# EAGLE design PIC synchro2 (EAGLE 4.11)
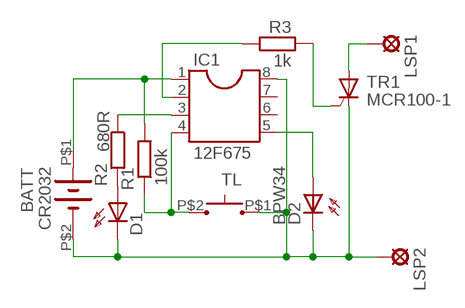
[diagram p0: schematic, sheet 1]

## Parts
BATT  CR2032  BATT_CR2032-1  [CR2032_HOLDER]
D1  LED3MM  [LED3MM]
D2  BPW34  BP104  [BP104]
IC1  12F675  DIL8  [DIL08]
LSP1  LSP13  [LSP13]
LSP2  LSP13  [LSP13]
R1  100k  R10-3  [R10_N]
R2  680R  R10-3  [R10_N]
R3  1k  R10-3  [R10_N]
TL  TLACITKO3-1  [TLACITKO3]
TR1  MCR100-1  [TO92-2]

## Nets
N$1: BATT.P$1(+) IC1.1 R1.2
N$2: BATT.P$2(-) D1.K(C) D2.K(C) IC1.8 LSP2.MP TL.P$1(P) TR1.C
N$3: IC1.2 R3.1
N$5: IC1.3 R2.1
N$6: D1.A R2.2
N$7: R3.2 TR1.G
N$8: D2.A IC1.5
N$10: LSP1.MP TR1.A
N$11: IC1.4 R1.1 TL.P$2(S)
Unconnected: IC1.6 IC1.7

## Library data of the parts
BATT = dusan:BATT_CR2032
D1 = led:LED3MM: LED
D2 = opto-trans-siemens:BP104: PHOTO DIODE
IC1 = dil:DIL8: SOCKET DIL8
LSP1 LSP2 = solpad:LSP13: SOLDER PAD
R1-R3 = dusan:R10
TL = dusan:TLACITKO3
TR1 = dusan:MCR100

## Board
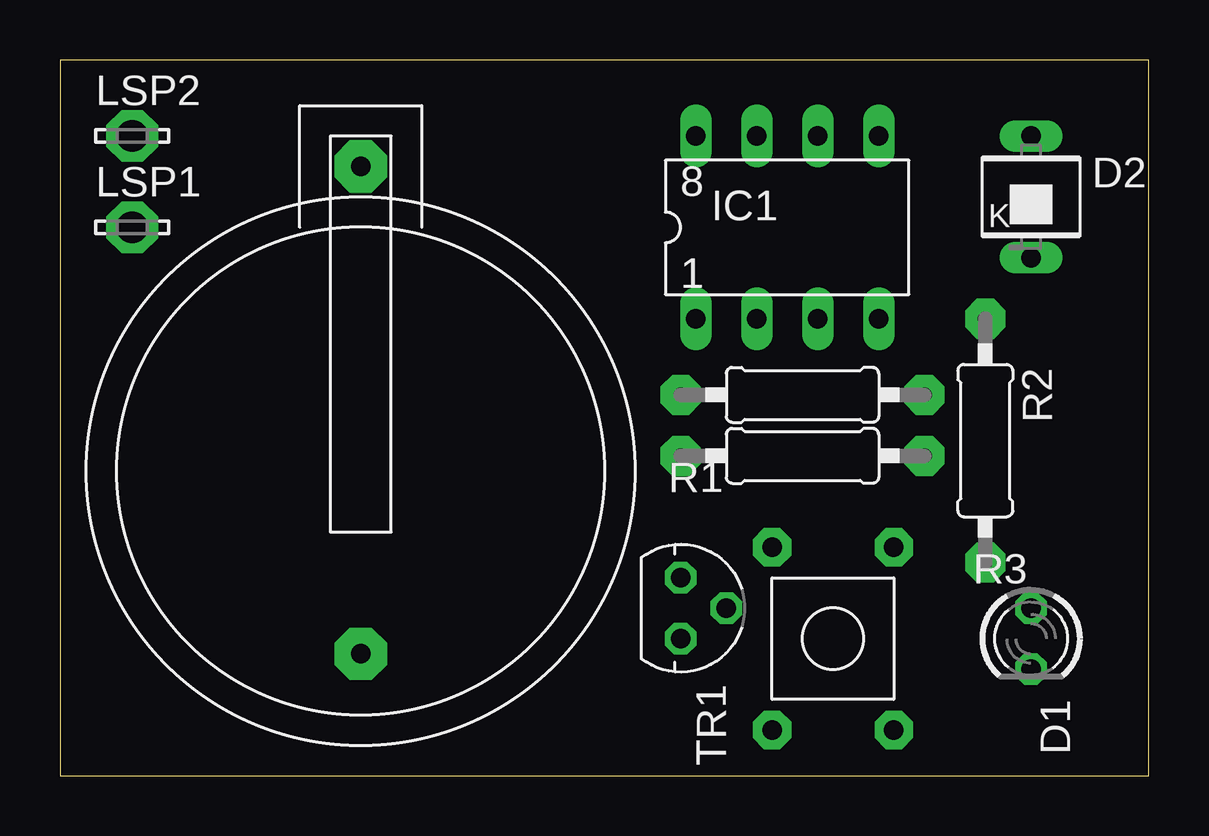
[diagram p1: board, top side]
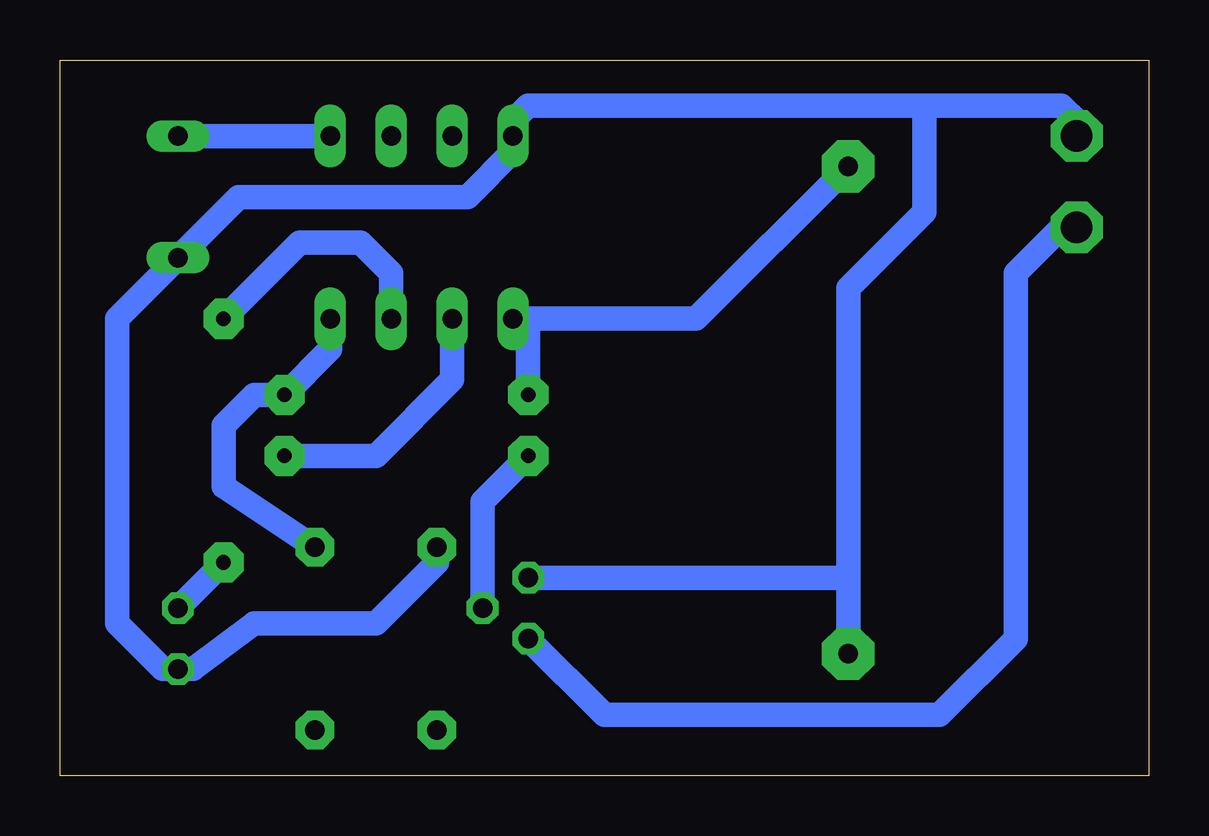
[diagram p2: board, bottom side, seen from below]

Size 45.39 x 29.83 mm. Coordinates in mm from the lower left corner, seen from the top.
Outline: 0,0 45.39,0 45.39,29.83 0,29.83 0,0
Copper layers 16: Bottom 0.035mm
Design rules "default": minimum track width 10mil, minimum drill 24mil, track to track 8mil, track to pad 8mil, pad to pad 8mil, via to via 8mil, smd to smd 8mil, copper to edge 40mil, drill to drill 8mil, minimum pad ring 10mil, minimum via ring 8mil, stop-mask expansion 0mil, vias tented up to drill 0mil, thermal gap 10mil

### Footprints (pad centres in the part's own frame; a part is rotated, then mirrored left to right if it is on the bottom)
CR2032_HOLDER = drill 0.813 pad 2.184 octagon: P$1 12.7,0; P$2 -7.62,0
LED3MM = drill 0.813 octagon: A -1.27,0; K 1.27,0
BP104 = drill 0.813 long: A 0,2.54; K 0,-2.54
DIL08 = drill 0.813 long: 1 -3.81,-3.81; 2 -1.27,-3.81; 3 1.27,-3.81; 4 3.81,-3.81; 5 3.81,3.81; 6 1.27,3.81; 7 -1.27,3.81; 8 -3.81,3.81
LSP13 = drill 1.321 pad 2.159 octagon: MP 0,0
R10_N = drill 0.61 pad 1.676 octagon: 1 -5.08,0; 2 5.08,0
TLACITKO3 = drill 0.813 pad 1.6 octagon: P$1 -2.54,3.81; P$2 2.54,3.81; P$3 -2.54,-3.81; P$4 2.54,-3.81
TO92-2 = drill 0.813 octagon: A 1.27,0; C -1.27,0; G 0,1.905

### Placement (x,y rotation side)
BATT  12.54,12.7 90 top
D1  40.48,5.71 270 top
D2  40.48,24.12 0 top
IC1  30.31,22.86 0 top
LSP1  3.01,22.86 0 top
LSP2  3.01,26.66 0 top
R1  30.95,15.87 180 top
R2  38.57,13.97 270 top
R3  30.95,13.33 180 top
TL  32.22,5.71 0 top
TR1  25.87,6.98 270 top

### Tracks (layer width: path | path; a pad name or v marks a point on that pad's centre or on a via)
N$1
  Bottom 1.016: R1.2 25.87,19.04 IC1.1 18.88,19.04 BATT.P$1
N$2
  Bottom 1.016: 9.36,27.93 3.64,27.93 3.01,27.3 LSP2.MP | 9.36,27.93 25.87,27.93 26.5,27.3 IC1.8 26.5,26.03 28.41,24.12 37.94,24.12 D2.K 43.02,19.04 43.02,6.34 41.11,4.44 D1.K 39.84,4.44 37.3,6.34 32.22,6.34 29.68,8.89 TL.P$1 | BATT.P$2 12.54,8.25 | 12.54,8.25 12.54,20.31 9.36,23.49 9.36,27.93 | 12.54,8.25 TR1.C
N$3
  Bottom 1.016: IC1.2 29.04,16.5 32.22,13.33 R3.1
N$5
  Bottom 1.016: IC1.3 31.58,20.95 32.85,22.22 35.39,22.22 R2.1
N$6
  Bottom 1.016: D1.A R2.2
N$7
  Bottom 1.016: R3.2 27.77,11.43 TR1.G
N$8
  Bottom 1.016: IC1.5 D2.A
N$10
  Bottom 1.016: TR1.A 22.7,2.54 8.73,2.54 5.55,5.71 5.55,20.95 3.64,22.86 LSP1.MP
N$11
  Bottom 1.016: TL.P$2 38.57,12.06 38.57,14.6 37.3,15.87 R1.1 34.12,17.77 IC1.4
